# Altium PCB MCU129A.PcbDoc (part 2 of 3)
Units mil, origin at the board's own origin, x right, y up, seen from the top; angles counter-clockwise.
Board outline 3092.79 x 1702.62 mil, 4 copper layers (Top Layer, L2_GND, L3_PWR/SIG, Bottom Layer), stack 58.736 mil thick; 213 components, 108 nets, 914 pads, 219 vias.
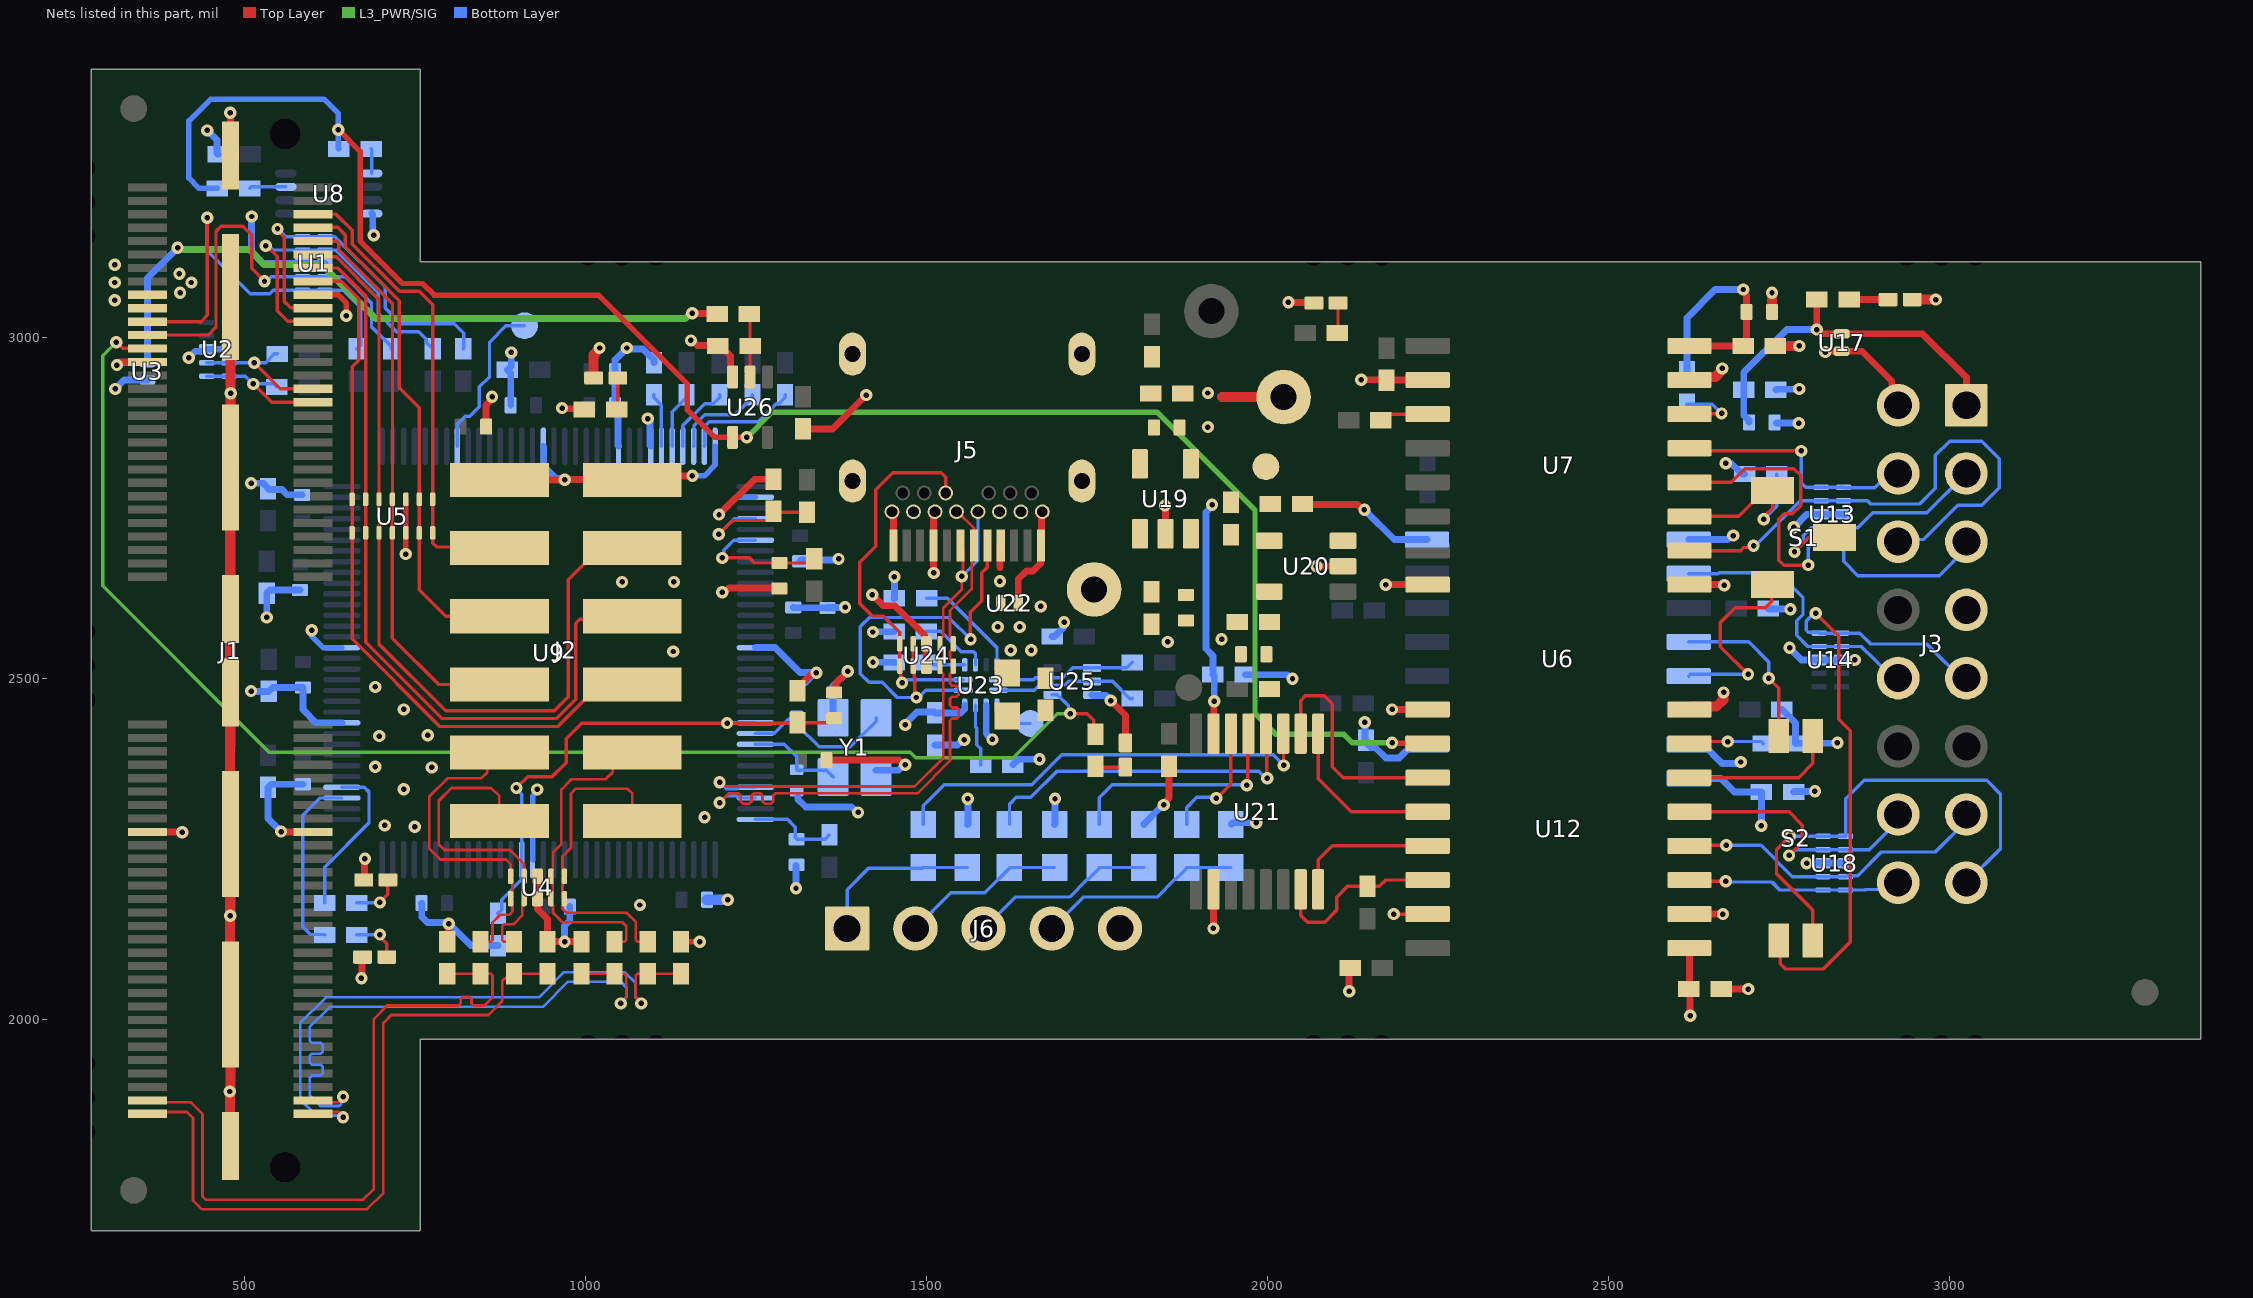
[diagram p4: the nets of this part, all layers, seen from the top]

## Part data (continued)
U6 U7: library part CMP-0091558-3, "Hot-swappable bidirectional I2C isolator with GPIO and enhanced EMC", Manufacturer="Texas Instruments", Operating Temperature Range=to
U8: library part CMP-0051824-2, "Dual Bus Buffer Gate With 3-State Outputs, DCU0008A (VSSOP-8)", F @ Nom Voltage(Max)(Mhz)=150, Generic Part Number=SN74LVC2G126, ICC @ Nom Voltage(Max)(mA)=0.01, Manufacturer="Texas Instruments", Operating Temperature Range="-40 to 125 C", Rating=Catalog, tpd @ Nom Voltage(Max)(ns)=9.8,4.9,4,3.2, Voltage(Nom)(V)=1.8,2.5,3.3,5
U9: library part CMP-0077953-1, "MSP432E401YTPDT, PDT0128A (TQFP-128)", Alternate Manufacturer="Texas Instruments", Alternate PartNumber=MSP432E401YTPDTR
U12: library part CMP-0076064-3, "High-Speed, Low-Power, Robust EMC Quad-Channel Digital Isolator, DW0016B (SOIC-16)", Alternate Manufacturer="Texas Instruments", Alternate PartNumber=ISO7741DW, Operating Temperature Range="-55 to 125 C", Rating=Catalog
U19: library part CMP-0091939-1, "Linear Voltage Regulator IC Positive Fixed 1 Output 300mA SOT-23-5", Digikey Part Number=296-47851-1-ND, Dropout Voltage=260mV, Manufacturer="Texas Instruments", Max Supply Voltage=5.5V, Min Supply Voltage=2V, Mouser Part Number=595-TLV70333DBVR, Nominal Supply Current=35-370uA, Operating Temperature Range="-40°C to +125°C", Output Voltage=3.3V
U20: library part CMP-0079364-1, "0.2% 50ppm/°C Drift Precision Series Voltage Reference with Shutdown Enable, DBV0005A (SOT-23-5)", Alternate Manufacturer="Texas Instruments", Alternate PartNumber=LM4120IM5X-4.1/NOPB
U21: library part CMP-0097843-1, "DAC 8-CH Resistor-String 12-bit 16-Pin TSSOP Rail", Digikey Part Number=DAC128S085CIMT/NOPB-ND, Manufacturer="Texas Instruments", Max Supply Voltage=5.5V, Min Supply Voltage=2.7V, Mouser Part Number=926-DAC128S085CIMTNO, Nominal Supply Current=460-650uA, Operating Temperature Range="-40°C to +125°C"
U23: library part CMP-0073635-2, "USB Type-C Configuration Channel Logic and Port Control, RWB0012A (X2QFN-12)", Alternate Manufacturer="Texas Instruments", Operating Temperature Range="-40 to 85 C", Rating=Catalog
U25: library part CMP-0051530-2, "Single 2-Input Positive-NOR Gate, DRL0005A, LARGE T&R", Alternate Manufacturer="Texas Instruments", F @ Nom Voltage(Max)(Mhz)=75, Generic Part Number=SN74AHC1G02, ICC @ Nom Voltage(Max)(mA)=0.01, Operating Temperature Range(C)="-40 to 125,-40 to 85", Rating=Catalog, tpd @ Nom Voltage(Max)(ns)=11.4,7.5, Voltage(Nom)(V)=3.3,5
U26: library part CMP-0051684-3, "Single Inverter, DCK0005A, LARGE T&R", F @ Nom Voltage(Max)(Mhz)=150, Generic Part Number=SN74LVC1G04, ICC @ Nom Voltage(Max)(mA)=0.01, Manufacturer="Texas Instruments", Operating Temperature Range(C)="-40 to 125,-40 to 85", Rating=Catalog, tpd @ Nom Voltage(Max)(ns)=7.5,5.2,4.2,3.7, Voltage(Nom)(V)=1.8,2.5,3.3,5
Y1: library part CMP-0094478-1, "Crystal 16 MHz ±20ppm Crystal 8pF 70 Ohms 4-SMD, No Lead", Digikey Part Number=732-830064296CT-ND, Frequency Stability=20ppm, Frequency_Fixed=16MHz, Load Capacitance=8pF, Manufacturer=Wurth, Mouser Part Number=710-830064296, Operating Temperature Range="-10°C to +70°C"
ZZ1: library part CMP-0003616-3
ZZ2: library part CMP-0077236-1
ZZ3: library part CMP-0077237-1
ZZ4: library part CMP-0077238-1

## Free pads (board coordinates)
  round 160 hole 160 unplated: 2(116.71,6382.89) 2(127.14,117.68) 2(4120.5,117.49) 2(4120.69,6382.89)

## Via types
v1: diameter 18, hole 8, Top Layer to Bottom Layer, tented both sides, 219 vias

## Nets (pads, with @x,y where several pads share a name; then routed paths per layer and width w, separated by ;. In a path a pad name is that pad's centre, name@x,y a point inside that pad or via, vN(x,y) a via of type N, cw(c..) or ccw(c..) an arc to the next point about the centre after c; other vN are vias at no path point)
3V3_OUT: J1.28 R53.2 U3.1 | length 1115.9
  Top Layer w10: v1(313.18,2960.12) 317.73,2964.68 J1.28@357.99,2964.68 ; v1(1156.62,3035.9) 1156.98,3035.54 1192.83,3035.54 R53.2@1193.19,3035.18
  L3_PWR/SIG w10: v1@402.07,3129.48 507.45,3129.48 529.79,3107.14 613.9,3107.14 692.62,3028.42 1146.97,3028.42 1154.45,3035.9 v1(1156.62,3035.9)
  Bottom Layer w10: v1(313.18,2960.12) 315.34,2960.12 319.01,2963.79 U3.1@357.99,2963.79 357.99,3087.93 v1(402.07,3132)
3V3_OUT_INV: R30.2 R31.2 U12.10 U26.4 | length 2699.8
  Top Layer w8: v1(637.81,3305.18) 669.7,3273.29 669.7,3142.25 732.24,3079.71 761.47,3079.71 778.61,3062.57 1019.51,3062.57 1149.25,2932.83 1149.25,2894.64 1189.81,2854.08 U26.4@1215.84,2854.08 1215.94,2854.18 v1(1236.81,2854.18) ; v1(2182.81,2406.18) 2183.31,2405.68 2234.44,2405.68 U12.10@2234.94,2405.18
  L3_PWR/SIG w8: v1(1236.81,2854.18) 1273.81,2891.18 1837.87,2891.18 1981.77,2747.28 1981.77,2448.99 2011.84,2418.92 2111.86,2418.92 2124.6,2406.18 v1(2182.81,2406.18)
  Bottom Layer w8: R31.2@460.56,3219.18 433.72,3219.18 418.81,3234.09 418.81,3318.18 450.81,3350.18 616.81,3350.18 637.81,3329.18 v1(637.81,3305.18) 637.81,3277.94 R30.2@638.56,3277.18
15W_PD: J1.26 R52.2 U25.4 | length 2066.4
  Top Layer w5: v1(312.19,2993.45) 313.18,2993.45 321.95,2984.68 J1.26@357.68,2984.68 ; v1(1710.81,2449.18) 1735.81,2449.18 1745.49,2439.5 1745.49,2421.5 R52.2@1747.81,2419.18
  L3_PWR/SIG w5: v1(312.19,2993.45) 292.31,2973.57 292.31,2636.52 536.15,2392.68 1476.47,2392.68 1484.47,2384.68 1627.31,2384.68 1691.81,2449.18 v1(1710.81,2449.18)
  Bottom Layer w5: U25.4@1684.67,2476.71 1691.96,2476.71 1708.32,2460.35 1708.32,2451.67 v1(1710.81,2449.18)
+5V0: C49.1 C52.2 C53.2 C59.2 J1.18 J1.20 J5.A4 J5.A9 J5.B4 J5.B9 L3.1 R39.2 R40.2 R46.1 R49.1 TP3.1 U19.1 U19.3 U22.1 U23.12 | length 325.4
  Top Layer w10: v1(965.86,2897.13) 966.87,2896.13 997.61,2896.13 R39.2@998.61,2895.12 ; v1(1510.61,2655.38) J5.A9@1510.61,2695.49 1510.61,2743.13 J5.B4@1512.57,2745.1 ; 1608.12,2663.51 1608.12,2694.59 J5.A4@1609.03,2695.49
  Bottom Layer w10: v1(1421.58,2568.73) 1422.04,2569.19 1452.27,2569.19 R46.1@1452.73,2569.66 ; R49.1@1452.73,2617.73 R49.1@1453.19,2618.18 ; R49.1@1453.19,2618.18 v1(1453.16,2649.76) ; v1@1468.81,2432.21 v1(1469.09,2432.49) 1469.09,2434.63 1486.01,2451.56 1511.43,2451.56 C59.2@1512.81,2450.18 1550.38,2450.18 1556.24,2456.04 U23.12@1556.24,2461.46
  other v1: 1623.81,2542.18 1653.81,2542.18 1604.81,2576.18 1636.81,2576.18 1667.81,2606.18 1607.81,2643.18 309.81,3055.18 405.81,3066.18 309.81,3081.18 422.47,3081.18 404.81,3094.18 309.81,3107.18
+5V0_A: C56.1 C57.2 L3.2 TP6.1 U20.3 U20.4 U21.7 | length 344.7
  Top Layer w10: U21.7@1920.89,2419.74 1921.43,2420.28 1921.43,2466.81 v1(1921.97,2467.34)
  Bottom Layer w10: v1(1918.81,2755.18) 1918.81,2753.32 1909.81,2744.32 1909.81,2544.18 1920.19,2533.8 C57.2@1920.19,2506.18 1921.97,2504.4 v1(1921.97,2467.34)
A_IN1_CONN: C1.2 J1.119 R7.2 | length 909.5
  Top Layer w4: J1.119@600.99,1862.32 603.83,1865.16 638.81,1865.16 644.81,1859.16 v1(644.81,1857.16) ; v1(1081.96,2024.18) 1073.96,2032.18 1073.96,2065.22 1076.3,2067.56 R7.2@1091.46,2067.56 C1.2@1140.46,2067.56
  Bottom Layer w4: v1(644.81,1857.16) 642.13,1859.84 605.67,1859.84 581.81,1883.7 581.81,1958.18 581.81,1995.18 619.81,2033.18 931.81,2033.18 968.65,2070.03 1057.65,2070.03 1073.96,2053.71 1073.96,2033.52 1081.96,2025.52 v1(1081.96,2024.18)
A_IN2_CONN: C3.1 J1.117 R9.2 | length 909.7
  Top Layer w4: J1.117@600.99,1882 603.83,1879.16 638.81,1879.16 644.81,1885.16 v1(644.81,1887.16) ; C3.1@994.46,2067.56 R9.2@1042.46,2067.56 1057.62,2067.56 1059.96,2065.22 1059.96,2032.18 v1(1051.96,2024.18)
  Bottom Layer w4: v1(644.81,1887.16) 642.13,1884.48 642.13,1876.79 639.18,1873.84 611.47,1873.84 595.81,1889.5 595.81,1897.16 595.81,1915.16 599.01,1918.36 611.82,1918.36 615.02,1921.56 615.02,1931.16 611.82,1934.36 599.01,1934.36 595.81,1937.56 595.81,1947.16 599.01,1950.36 611.82,1950.36 615.02,1953.56 615.02,1963.16 611.82,1966.36 599.01,1966.36 595.81,1969.56 595.81,1983.85 595.81,1989.38 625.61,2019.18 937.61,2019.18 974.45,2056.03 1051.85,2056.03 1059.96,2047.91 1059.96,2033.52 1051.96,2025.52 v1(1051.96,2024.18)
A_IN5_CONN: C2.1 J1.120 R8.1 | length 1024
  Top Layer w4: J1.120@357.99,1862.32 360.84,1865.16 416.03,1865.16 424.81,1856.38 424.81,1735.21 437.49,1722.53 680.06,1722.53 703.81,1746.27 703.81,1995.61 715.38,2007.18 812.01,2007.18 857.76,2007.18 878.11,2027.53 878.11,2057.03 888.64,2067.56 R8.1@895.46,2067.56 C2.1@944.46,2067.56
A_IN6_CONN: C4.1 J1.118 R10.1 | length 1023.1
  Top Layer w4: J1.118@357.99,1882 360.84,1879.16 421.83,1879.16 438.81,1862.18 438.81,1741 443.28,1736.53 674.26,1736.53 689.81,1752.07 689.81,2001.41 709.58,2021.18 812.01,2021.18 814.01,2021.18 817.21,2024.38 817.21,2030.43 820.41,2033.63 830.01,2033.63 833.21,2030.43 833.21,2024.38 836.41,2021.18 841.34,2021.18 851.96,2021.18 863.96,2033.18 863.96,2065.22 861.62,2067.56 R10.1@846.46,2067.56 C4.1@797.46,2067.56
ANALOG_IN_1: J2.1 R7.1 U4.1 U4.10 | length 475.2
  Top Layer w4: J2.1@1068.81,2291.83 1068.81,2331.94 1061.8,2338.95 985.8,2338.95 978.81,2331.96 978.81,2252.38 966.34,2239.91 966.34,2222.08 967.24,2221.18 967.24,2212.56 U4.1@969.18,2210.62 967.24,2208.68 967.24,2200.06 966.34,2199.15 966.34,2189.21 967.24,2188.3 967.24,2179.68 U4.10@969.18,2177.74 969.18,2170.56 966.42,2167.8 966.42,2162.97 972.2,2157.18 1060.28,2157.18 1073.96,2143.5 1073.96,2117.15 1076.3,2114.8 R7.1@1091.46,2114.8
ANALOG_IN_2: J2.3 R9.1 U4.2 U4.9 | length 474.8
  Top Layer w4: R9.1@1042.46,2114.8 1057.62,2114.8 1059.96,2117.15 1059.96,2137.7 1054.48,2143.18 966.4,2143.18 952.42,2157.17 952.42,2167.64 949.49,2170.56 U4.9@949.49,2177.74 951.43,2179.68 951.43,2188.3 952.34,2189.21 952.34,2199.15 951.43,2200.06 951.43,2208.68 U4.2@949.49,2210.62 951.43,2212.56 951.43,2221.18 952.34,2222.08 952.34,2245.71 964.81,2258.18 964.81,2337.76 980,2352.95 1029.93,2352.95 1040.15,2363.17 1040.15,2368.83 1063.15,2391.83 J2.3@1068.81,2391.83
ANALOG_IN_5: J2.2 R8.2 U4.4 U4.7 | length 492.3
  Top Layer w4: J2.2@873.93,2291.83 873.93,2328.06 861.81,2340.18 803.82,2340.18 785.03,2321.39 785.03,2257.37 793.22,2249.18 889.37,2249.18 910.12,2228.43 U4.4@910.12,2210.62 908.19,2208.68 908.19,2200.06 907.28,2199.15 907.28,2189.21 908.19,2188.3 908.19,2179.68 U4.7@910.12,2177.74 908.19,2175.81 908.19,2167.18 907.28,2166.28 907.28,2153.07 894.39,2140.18 880.96,2140.18 877.96,2137.18 877.96,2117.15 880.3,2114.8 R8.2@895.46,2114.8
ANALOG_IN_6: J2.4 R10.2 U4.5 U4.6 | length 492.3
  Top Layer w4: R10.2@846.46,2114.8 861.62,2114.8 863.96,2117.15 863.96,2142.98 875.16,2154.18 888.59,2154.18 893.28,2158.87 893.28,2166.28 892.38,2167.18 892.38,2175.81 U4.6@890.44,2177.74 892.38,2179.68 892.38,2188.3 893.28,2189.21 893.28,2199.15 892.38,2200.06 892.38,2208.68 U4.5@890.44,2210.62 890.44,2228.32 883.57,2235.18 787.42,2235.18 771.03,2251.57 771.03,2327.19 798.02,2354.18 847.26,2354.18 856.25,2363.17 856.25,2372.51 J2.4@873.93,2390.18
DAC_CLK: U12.13 U21.16 | length 212.4
  Top Layer w5: U21.16@2074.44,2191.39 2074.44,2234.81 2094.81,2255.18 U12.13@2234.94,2255.18
DAC_PICO: U12.12 U21.1 | length 246.7
  Top Layer w5: U21.1@2074.44,2419.74 2074.44,2353.66 2122.91,2305.18 U12.12@2234.94,2305.18
DAC_POCI: U12.11 U21.2 | length 341
  Top Layer w5: U21.2@2048.85,2419.74 2048.85,2468.22 2055.72,2475.09 2083.47,2475.09 2095.31,2463.25 2095.31,2371.28 2111.41,2355.18 U12.11@2234.94,2355.18
DAC_STE: R27.1 U12.14 U21.15 | length 265.3
  Top Layer w5: U21.15@2048.85,2191.39 2048.85,2153.07 2058.74,2143.18 2083.81,2143.18 2101.81,2161.18 2101.81,2180.18 2117.43,2195.8 R27.1@2146.81,2195.8 2164.03,2195.8 2173.41,2205.18 U12.14@2234.94,2205.18
DBG_ID4: R15.2 U9.63 | length 168.9
  Bottom Layer w5: U9.63@1174.52,2841.18 1174.83,2841.48 1174.83,2870.67 1181.39,2877.24 1253.49,2877.24 1279.56,2903.31 1283.5,2903.31 1292.81,2912.62 R15.2@1292.81,2916.56
DBG_ID5: R16.2 U9.62 | length 137.1
  Bottom Layer w5: U9.62@1158.78,2841.18 1159.33,2841.73 1159.33,2871.7 1174.87,2887.24 1219.43,2887.24 1235.5,2903.31 1244.81,2912.62 R16.2@1244.81,2916.56
DBG_ID6: R17.2 U9.61 | length 105.1
  Bottom Layer w5: U9.61@1143.03,2841.18 1143.03,2871.55 1174.79,2903.31 1187.5,2903.31 1196.81,2912.62 R17.2@1196.81,2916.56
DBG_ID7: R18.2 U9.60 | length 84.2
  Bottom Layer w5: U9.60@1127.28,2841.18 1127.28,2891.44 1148.46,2912.62 R18.2@1148.46,2916.56
DIGITAL_IO_2: J1.15 J2.5 U5.1 U5.14 | length 1069.6
  Top Layer w5: J1.15@600.99,3082.79 642.19,3082.79 667.75,3057.22 667.75,3040.43 667.93,3040.26 667.93,3024.93 667.75,3024.76 667.75,2967.39 658.07,2957.71 U5.14@658.07,2763.39 U5.1@658.07,2714.18 658.07,2614.18 658.07,2558.54 786.43,2430.18 959.72,2430.18 1021.37,2491.83 J2.5@1068.81,2491.83
DIGITAL_IO_3: J1.13 J2.7 U5.2 U5.13 | length 1165.8
  Top Layer w5: J1.13@600.99,3102.47 636.64,3102.47 677.75,3061.37 677.75,3044.57 677.93,3044.4 677.93,3020.79 677.75,3020.62 U5.13@677.75,2763.39 U5.2@677.75,2714.18 677.75,2614.18 677.75,2554.01 789.88,2441.88 957.28,2441.88 985.81,2470.41 985.81,2581.27 991.8,2587.26 1064.24,2587.26 J2.7@1068.81,2591.83
DIGITAL_IO_4: J1.11 J2.9 U5.3 U5.12 | length 1240.2
  Top Layer w5: J1.11@600.99,3122.16 604.49,3118.66 634.61,3118.66 697.44,3055.82 U5.12@697.44,2763.39 U5.3@697.44,2714.18 697.44,2614.18 697.44,2550.77 795.02,2453.18 954.44,2453.18 974.81,2473.55 974.81,2645.27 1021.37,2691.83 J2.9@1068.81,2691.83
DIGITAL_IO_5: J1.9 J2.6 U5.4 U5.11 | length 835.1
  Top Layer w5: J1.9@600.99,3141.84 635.27,3141.84 638.2,3138.92 638.2,3129.2 717.25,3050.15 U5.11@717.25,2763.52 ; U5.11@717.12,2763.39 U5.4@717.12,2714.18 717.12,2559.87 785.16,2491.83 J2.6@873.93,2491.83
DIGITAL_IO_7: J1.7 J2.8 U5.6 U5.9 | length 750.7
  Top Layer w5: J1.7@600.99,3161.53 601.49,3162.03 637.03,3162.03 648.2,3150.86 648.2,3133.34 727.25,3054.29 727.25,2927 756.49,2897.76 U5.9@756.49,2763.39 U5.6@756.49,2714.18 756.49,2630.55 795.22,2591.83 J2.8@873.93,2591.83
DIGITAL_IO_8: J1.5 J2.10 U5.7 U5.8 | length 692.5
  Top Layer w5: J1.5@600.99,3181.21 601.4,3181.63 634.1,3181.63 658.2,3157.53 658.2,3137.48 727.48,3068.21 756.7,3068.21 776.18,3048.74 U5.8@776.18,2763.39 U5.7@776.18,2714.18 776.18,2699.18 781.91,2693.45 872.31,2693.45 J2.10@873.93,2691.83
GND: C1.1 C2.2 C3.2 C4.2 C5.1 C10.2 C11.1 C14.2 C16.1 C17.2 C19.1 C20.1 C21.1 C22.1 C23.1 C24.1 C25.1 C26.1 C27.1 C30.1 C31.1 C32.1 C33.1 C34.1 C35.1 C36.1 C37.2 C38.2 C39.2 C40.2 C43.2 C44.1 C45.2 C46.1 C47.2 C48.1 C49.2 C50.2 C51.1 C52.1 C53.1 C54.1 C55.1 C56.2 C57.1 C58.1 C59.1 C60.2 C61.2 C62.2 C63.2 C64.1 C65.1 J1.17 J1.77 J1.78 J1.A1 J1.A2 J1.A3 J1.A4 J1.A5 J1.A6 J1.A7 J1.A8 J2.11 J2.12 J5.A1 J5.A12 J5.B1 J5.B12 J5.M1 J5.M2 J5.S1 J5.S2 J5.S3 J5.S4 J6.5 LED1.2 LED2.2 LED3.2 LED4.2 LED5.2 R26.1 R40.1 R47.2 R48.1 R54.1 TP5.1 U1.3@585.43,3109.19 U1.8@618.31,3109.19 U2.3@444.81,2983.19 U2.8@477.69,2983.19 U3.2 U4.3@929.81,2210.62 U4.8@929.81,2177.74 U5.5 U5.10 U6.2 U6.8 U7.2 U7.8 U8.4 U9.10 U9.17 U9.48 U9.55 U9.58 U9.64 U9.66 U9.80 U9.114 U12.9 U12.15 U19.2 U19.4 U20.2 U21.10 U22.2 U23.10 U24.3@1500.22,2551.47 U24.8@1500.22,2518.59 U25.3 U26.3 Y1.2 Y1.4 | length 6954.5
  Top Layer w5: v1(2185.3,2155.18) U12.15@2234.94,2155.18
  Top Layer w8: J1.17@601.01,3063.13 638.08,3063.13 649.4,3051.81 v1(649.43,3032.59) ; v1(736.81,2683.08) U5.5@736.81,2714.18 U5.10@736.81,2763.39 ; C1.1@1140.46,2114.8 v1(1167.79,2114.8)
  Top Layer w10: J1.78@357.99,2275.7 358.27,2275.42 408.53,2275.42 v1(408.81,2275.14) ; J1.A1@479.49,3267.43 v1(479.49,3330.18) ; v1(553.81,2276.18) 554.29,2275.7 J1.77@600.99,2275.7 ; v1(671.66,2061.18) 672.52,2062.04 672.52,2091.32 LED1.2@673.38,2092.18 ; LED2.2@675.09,2205.18 675.95,2206.04 675.95,2235.32 v1(676.81,2236.18) ; C4.2@797.46,2114.8 798.64,2115.98 798.64,2140.01 v1(799.81,2141.18) ; C25.1@854.53,2869.83 854.53,2901.45 863.15,2910.08 v1(863.15,2913.59) ; J2.12@873.93,2791.83 969.45,2791.83 v1(969.81,2792.18) 1068.45,2792.18 J2.11@1068.81,2791.83 1074.68,2797.7 v1(1157,2797.7) ; U4.3@929.81,2210.62 U4.8@929.81,2177.74 929.81,2162.8 944.46,2148.15 C2.2@944.46,2114.8 v1(969.46,2114.8) C3.2@994.46,2114.8 C3.2@995.84,2116.18 ; v1(1154.81,2996.18) 1156.86,2996.18 1164.36,2988.68 1193.69,2988.68 R54.1@1194.19,2988.18 1198.12,2988.18 1212.97,2973.34 1212.97,2945.54 U26.3@1215.84,2942.66 ; v1(1195.91,2740.9) 1247.69,2792.68 C48.1@1275.81,2792.68 ; v1@1202.21,2628.58 v1(1200.81,2627.18) 1204.33,2627.18 1210.65,2633.5 C16.1@1285.14,2633.5 ; C45.2@1311.31,2482.8 1311.31,2486.74 1332.22,2507.65 1337.28,2507.65 v1(1338.81,2509.18) ; C65.1@1318.81,2866.56 1362.19,2866.56 v1(1411.81,2916.18) ; C32.1@1353.51,2381.18 1459.64,2381.18 1466.64,2374.18 v1(1468.81,2374.18) ; C44.1@1360.81,2482.8 1367.62,2489.61 1367.62,2493.99 v1(1384.81,2511.18) ; v1(1420.81,2623.18) 1436.81,2607.18 1454.28,2607.18 1497.34,2564.12 1497.34,2554.34 U24.3@1500.22,2551.47 U24.8@1500.22,2518.59 ; J5.B1@1449.58,2745.1 1451.55,2743.13 J5.A12@1451.55,2695.49 ; U22.2@1634.6,2611.18 1634.6,2646.1 1646.68,2658.18 1656.17,2658.18 1667.18,2669.19 1667.18,2694.59 J5.A1@1668.09,2695.49 1668.99,2696.4 1668.99,2744.04 J5.B12@1670.05,2745.1 ; v1(1770.31,2468.18) 1791.81,2446.69 LED5.2@1791.81,2406.18 ; v1(1847.81,2315.18) 1847.81,2317.35 1855.67,2325.2 C58.1@1855.67,2372.12 ; v1(1849.81,2754.18) 1850.41,2753.58 U19.2@1850.41,2712.82 ; v1(1920.81,2134.18) 1920.89,2134.27 U21.10@1920.89,2191.39 ; v1(2030.81,3052.18) 2031.31,3051.68 2067.59,3051.68 LED4.2@2068.09,3051.18 ; C56.2@2051.43,2756.18 2051.81,2755.8 2132.19,2755.8 2140.12,2747.88 v1(2142.28,2747.88) ; v1(2071.81,2665.18) U20.2@2110.94,2665.18 ; v1(2119.81,2042.18) 2119.81,2074.8 C17.2@2121.19,2076.18 ; v1@2136.81,2939.18 v1(2137.43,2938.56) 2173.81,2938.56 2174.19,2938.18 U7.2@2234.88,2938.18 ; v1(2173.42,2638.18) U7.8@2234.88,2638.18 ; v1(2182.81,2455.18) U12.9@2234.94,2455.18
  Top Layer w15: J1.A2@479.15,3060.29 J1.A2@479.49,3059.95 479.65,3059.79 479.65,2917.34 479.81,2917.18 479.65,2917.02 479.65,2810.11 J1.A3@479.49,2809.95 479.49,2683.1 479.31,2682.92 479.31,2602.66 J1.A4@479.49,2602.47 J1.A5@479.49,2480.03 479.49,2400.71 478.81,2400.03 479.15,2399.69 479.15,2272.89 J1.A6@479.49,2272.55 479.49,2154.71 478.81,2154.03 478.81,2153.03 v1(479.15,2152.69) 479.15,2022.89 J1.A7@479.49,2022.55 479.81,2022.23 479.81,1896.03 v1(478.81,1895.03) 479.15,1894.69 479.15,1815.41 J1.A8@479.49,1815.07 ; LED3.2@1012.09,2941.18 1012.09,2975.65 1020.81,2984.37 v1(1020.81,2985.18) ; 1933.81,2913.18 TP5.1@2023.81,2913.18
  Bottom Layer w5: C11.1@1308.81,2226.48 C11.1@1309.81,2227.48
  Bottom Layer w8: v1(598.81,2571.18) 598.81,2562.54 615.38,2545.97 642.97,2545.97 U9.17@643.03,2545.91 ; U9.114@922.56,2234.88 922.56,2328.26 929.58,2335.28 v1(929.58,2337.95) ; v1(1157,2797.7) 1157.73,2798.44 1158.48,2797.69 1174.37,2797.69 1190.27,2813.6 U9.64@1190.27,2841.18 ; v1(1195.91,2740.9) 1221.39,2766.38 U9.66@1249.33,2766.38
  Bottom Layer w10: v1(310.81,2925.18) 323.83,2938.2 U3.2@357.99,2938.2 ; v1(418.48,2970.73) 418.75,2970.73 428.48,2980.46 442.09,2980.46 U2.3@444.81,2983.19 U2.8@477.69,2983.19 ; v1(445.81,3304.18) 459.86,3290.13 459.86,3270.89 C5.1@461.56,3269.18 ; v1(509.81,2482.18) 510.43,2481.56 C39.2@535.81,2481.56 541.73,2487.48 C22.1@585.81,2487.48 585.81,2455.18 605.32,2435.67 U9.10@643.03,2435.67 ; v1(509.89,2786.78) 528,2786.78 534.81,2779.97 C37.2@534.81,2778.8 535.81,2777.8 555.01,2777.8 562.93,2769.88 C24.1@584.81,2769.88 ; v1(510.81,3177.95) 510.58,3177.72 510.58,3126.35 527.73,3109.19 U1.3@585.43,3109.19 U1.8@618.31,3109.19 ; v1(532.81,2590.18) C38.2@532.81,2625.56 537.49,2630.24 C23.1@581.81,2630.24 ; v1(553.81,2276.18) 534.81,2295.18 C40.2@534.81,2340.94 539.36,2345.49 C46.1@586.05,2345.49 ; U8.4@686.81,3182.13 687.42,3182.13 688.26,3181.29 688.26,3151.98 v1(689.7,3150.53) ; C35.1@759.81,2171.18 760.18,2170.81 760.18,2150.81 768.28,2142.71 798.28,2142.71 832.05,2108.94 C43.2@871.81,2108.94 ; C26.1@890.49,2901.18 890.49,2948.26 C47.2@885.56,2953.18 891.31,2958.93 v1(891.31,2978.6) ; U9.48@938.3,2841.18 939.12,2840.37 939.12,2811.37 956.78,2793.71 968.28,2793.71 v1(969.81,2792.18) ; v1(969.46,2114.8) 969.46,2138.14 977.21,2145.89 C34.1@977.21,2166.18 ; U9.55@1048.54,2841.18 1047.99,2841.73 1047.99,2896.7 C27.1@1043.51,2901.18 C21.1@1043.51,2951.18 1043.51,2967.88 v1(1060.81,2985.18) 1062.34,2983.65 1084.55,2983.65 1100.46,2967.74 R26.1@1100.46,2963.8 ; v1@1078.51,2166.99 v1(1080.04,2168.52) ; v1(1091.35,2881.62) 1094.97,2878 1094.97,2841.99 U9.58@1095.78,2841.18 ; U9.80@1249.33,2545.91 1278.33,2545.91 1314.81,2509.42 1338.57,2509.42 v1(1338.81,2509.18) 1336.64,2509.18 1321.01,2493.55 1318.12,2493.55 1311.31,2486.74 C19.1@1311.31,2482.8 ; C31.1@1304.81,2604.88 1305.31,2604.38 1354.31,2604.38 C36.1@1354.81,2603.88 1355.46,2604.53 1380.16,2604.53 v1(1380.81,2605.18) ; v1(1308.81,2193.18) C11.1@1308.81,2226.48 ; C20.1@1311.31,2327.94 1311.31,2324 1323.12,2312.19 1389.95,2312.19 1397.96,2304.18 v1(1399.81,2304.18) ; C30.1@1314.81,2672.48 1316.48,2674.15 1369.51,2674.15 v1(1371.18,2675.83) ; Y1.4@1363.31,2452.8 1363.31,2489.68 v1(1384.81,2511.18) ; v1(1421.71,2524.48) 1421.86,2524.33 1453.03,2524.33 R47.2@1453.19,2524.18 ; Y1.2@1426.3,2366.18 1459.25,2366.18 1467.25,2374.18 v1(1468.81,2374.18) ; C59.1@1512.81,2402.94 1513.05,2403.18 1545.53,2403.18 1553.29,2410.94 v1(1555.46,2410.94) ; C60.2@1560.09,2286.49 1560.81,2287.21 v1(1560.81,2324.18) ; U23.10@1587.74,2461.46 1587.74,2420.25 v1(1596.81,2411.18) ; R48.1@1626.76,2374.18 1634.76,2382.18 v1(1665.81,2382.18) ; C64.1@1684.19,2562.18 1688.12,2562.18 1700.28,2574.34 1700.28,2581.65 v1(1701.81,2583.18) ; C61.2@1687.84,2286.49 1688.56,2287.21 v1(1688.56,2324.18) ; U25.3@1742.94,2476.71 1743.85,2475.8 1763.19,2475.8 1770.31,2468.68 v1(1770.31,2468.18) ; C62.2@1818.83,2286.49 1818.83,2287.47 1846.54,2315.18 v1(1847.81,2315.18) ; C63.2@1946.9,2286.85 1949.24,2289.18 v1(1983.81,2289.18) ; C57.1@1967.43,2506.18 2028.64,2506.18 2034.64,2500.18 v1(2036.81,2500.18) ; v1(2142.28,2747.88) 2185.98,2704.18 U6.8@2233.88,2704.18 ; v1@2142.81,2437.18 v1(2142.81,2436.37) 2143.31,2435.87 C10.2@2143.31,2410.3 ; C10.2@2144.81,2409.8 2144.81,2405.87 2151.62,2399.06 2158.69,2399.06 2173.56,2384.18 2193.21,2384.18 2213.21,2404.18 U6.2@2233.88,2404.18
  Bottom Layer w15: C33.1@1177.43,2176.18 v1(1208.81,2176.18)
  other v1: 749.81,2283.18 705.81,2285.18 1174.81,2297.18 733.81,2338.18 774.81,2370.18 691.81,2371.18 697.81,2416.18 768.81,2417.18 733.81,2455.18 691.81,2488.18 1128.81,2540.18 1853.81,2554.18 1932.81,2558.18 1053.81,2642.18 1129.81,2642.18 1912.81,2869.18 479.91,2918.84 1912.81,2919.18
GNDH: C9.1 C12.1 C13.1 C15.1 C18.1 J3.2 J3.7 LED6.2 U6.9 U6.15 U7.9 U7.15 U12.2 U12.8 U13.3@2811.93,2741.5 U13.8@2844.81,2741.5 U14.3@2841.81,2527.81 U14.8@2808.93,2527.81 U17.2 U18.3@2814.81,2229.87 U18.8@2847.68,2229.87 | length 983
  Top Layer w10: U7.9@2618.74,2638.18 2668.81,2638.18 v1(2669.81,2637.18) ; U12.2@2618.8,2155.18 v1(2667.81,2155.18) ; C18.1@2665.05,2045.18 v1(2704.81,2045.18) ; v1(2817.81,2979.18) 2819.01,2980.39 U17.2@2841.81,2980.39 2872.06,2980.39 2915.3,2937.15 2915.3,2902.88 J3.2@2920.45,2897.73
  Top Layer w15: U7.15@2618.74,2938.18 2623.05,2942.49 2656.52,2942.49 2666.23,2952.21 2666.23,2954.61 v1(2666.81,2955.18) ; U12.8@2618.8,2455.18 2623.11,2459.49 2658.52,2459.49 2668.23,2469.21 2668.23,2479.61 v1(2668.81,2480.18) ; C13.1@2739.81,3043.18 v1(2739.81,3066.18) ; C15.1@2744.81,2988.18 v1(2779.95,2988.18) ; LED6.2@2945.44,3056.18 v1(2979.81,3056.18)
  Bottom Layer w10: U6.15@2617.74,2404.18 2638.41,2404.18 2666.41,2376.18 2691.81,2376.18 v1(2693.81,2378.18) ; U6.9@2617.74,2704.18 2674.64,2704.18 2680.64,2710.18 v1(2682.81,2710.18) ; C12.1@2746.56,2874.99 v1(2779,2874.99) ; v1(2765.51,2545.86) 2765.51,2545.11 2782.81,2527.81 U14.3@2841.81,2527.81 v1(2861.31,2527.81) ; C9.1@2771.43,2334.18 2771.93,2334.68 2802.31,2334.68 v1(2802.81,2335.18) ; v1(2771.81,2722.18) 2791.12,2741.5 U13.3@2811.93,2741.5 U13.8@2844.81,2741.5 U13.8@2845.87,2740.43 ; v1(2790.49,2229.87) U18.3@2814.81,2229.87 U18.8@2847.68,2229.87 ; U18.8@2847.8,2229.79 U18.8@2853.8,2229.79
IO_TGT_V: C12.2 J3.1 L1.1 R32.2 U17.1 | length 542.5
  Top Layer w10: R32.2@2805.48,3056.18 v1(2805.48,3012.19) 2807.64,3012.19 2813.86,3005.98 U17.1@2841.81,3005.98 2960.71,3005.98 3024.81,2941.87 J3.1@3024.81,2901.18
  Bottom Layer w10: C12.2@2706.11,2876.18 2706.11,2879.13 2698.31,2886.93 L1.1@2698.31,2923.99 2698.31,2948.99 2761.51,3012.19 v1(2805.48,3012.19)
IO_TGT_V_FL: C9.2 C13.2 C15.2 C18.2 L1.2 R13.2 R14.2 R20.2 R23.2 R28.2 U6.16 U7.16 U12.1 | length 831.1
  Top Layer w10: U7.16@2618.74,2988.18 C15.2@2697.56,2988.18 2702.49,2993.1 C13.2@2702.49,3038.18 2702.49,3062.5 2697.56,3067.42 v1(2697.56,3070.94) ; U12.1@2618.8,2105.18 2618.8,2046.17 C18.2@2617.81,2045.18 2619.81,2043.18 v1(2619.81,2006.18)
  Bottom Layer w10: R23.2@2615.09,2949.99 2615.09,3029.47 2656.56,3070.94 v1(2697.56,3070.94) ; U6.16@2617.74,2354.18 2664.81,2354.18 2684.81,2334.18 C9.2@2724.19,2334.18 v1(2724.19,2284.8) ; v1(2671.81,2816.18) 2679.63,2816.18 2695.63,2800.18 R20.2@2699.56,2800.18 ; R14.2@2734.43,2603.18 2734.93,2602.68 2766.31,2602.68 v1(2766.81,2602.18) ; L1.2@2745.56,2923.99 2746.15,2924.59 2779.21,2924.59 v1(2779.81,2925.18) ; R13.2@2754.43,2455.18 2774.43,2435.18 R28.2@2774.43,2405.18 2774.93,2405.68 2835.31,2405.68 v1(2835.81,2406.18)
MCU_CLK_ISO: J3.13 U12.4 U18.2 U18.9 | length 464
  Top Layer w5: U12.4@2618.8,2255.18 2619.8,2256.18 v1(2672.81,2256.18)
  Bottom Layer w5: v1(2672.81,2256.18) 2723.74,2256.18 2769.74,2210.18 U18.2@2814.81,2210.18 U18.9@2847.68,2210.18 2849.12,2211.62 2865.25,2211.62 2899.81,2246.18 2979.3,2246.18 3024.3,2291.18 J3.13@3029.81,2291.18
MCU_PICO_ISO: J3.14 U12.5 U18.4 U18.7 | length 409.7
  Top Layer w5: U12.5@2618.8,2305.18 2764.81,2305.18 2784.31,2285.68 2784.31,2260.62 v1(2764.89,2241.2)
  Bottom Layer w5: v1(2764.89,2241.2) 2765.96,2241.2 2774.32,2249.55 U18.4@2814.81,2249.55 U18.7@2847.68,2249.55 2882.67,2249.55 2919.3,2286.18 J3.14@2929.81,2286.18
MCU_POCI_ISO: S2.1 U12.6 | length 229.7
  Top Layer w5: U12.6@2618.8,2355.18 2778.81,2355.18 2799.81,2376.18 S2.1@2799.81,2416.18
MCU_POCI_ISO_SW: J3.15 S2.4 U18.5 U18.6 | length 717.5
  Top Layer w5: v1(2765.81,2269.18) 2746.39,2249.76 2746.39,2214.6 2799.81,2161.18 S2.4@2799.81,2116.18
  Bottom Layer w5: v1(2765.81,2269.18) U18.5@2814.78,2269.21 ; U18.5@2814.81,2269.24 U18.6@2847.68,2269.24 2847.68,2324.06 2875.16,2351.53 3054.46,2351.53 3074.81,2331.18 3074.81,2251.18 J3.15@3024.81,2201.18
MCU_RXD: J1.33 R6.2 U2.1 U2.10 | length 208.4
  Top Layer w5: v1(513.12,2932.46) 539.96,2905.62 J1.33@600.99,2905.62
  Bottom Layer w5: U2.1@444.81,2943.82 U2.10@477.69,2943.82 501.14,2943.82 512.5,2932.46 v1(513.12,2932.46) 543.33,2932.46 R6.2@547.71,2928.08
MCU_RXD_ISO: S2.2 U6.12 | length 244.3
  Top Layer w5: v1(2735.18,2500.77) 2749.81,2486.14 S2.2@2749.81,2416.18
  Bottom Layer w5: U6.12@2617.74,2554.18 2705.81,2554.18 2735.18,2524.81 v1(2735.18,2500.77)
MCU_RXD_ISO_SW: J3.9 S2.3 U14.1 U14.10 | length 963.8
  Top Layer w5: S2.3@2749.81,2116.18 2751.81,2114.18 2751.81,2082.64 2759.77,2074.68 2814.77,2074.68 2854.31,2114.22 2854.31,2424.06 2837.55,2440.82 2837.55,2562.44 v1(2803.81,2596.18)
  Bottom Layer w5: v1(2803.81,2596.18) 2801.11,2596.18 2789.81,2584.88 2789.81,2571.55 2792.74,2568.62 2807.5,2568.62 U14.10@2808.93,2567.18 U14.1@2841.81,2567.18 2868.31,2567.18 2884.31,2551.18 2967,2551.18 3024.81,2493.37 J3.9@3024.81,2491.18 ; J3.9@3007,2491.18 J3.9@3009.81,2491.18
MCU_STE_ISO: J3.16 U12.3 U18.1 U18.10 | length 312.4
  Top Layer w5: U12.3@2618.8,2205.18 2620.8,2203.18 v1(2671.81,2203.18)
  Bottom Layer w5: v1(2671.81,2203.18) 2672.81,2202.18 2739.81,2202.18 2751.49,2190.5 U18.1@2814.81,2190.5 U18.10@2847.68,2190.5 2876.5,2190.5 2877.19,2191.18 J3.16@2924.81,2191.18
MCU_TCK: J1.22 R3.1 U1.1 U1.10 | length 610.2
  Top Layer w5: J1.22@358.19,3023.93 436.58,3023.93 445.81,3033.16 v1(445.81,3176.22)
  Bottom Layer w5: v1(445.81,3176.22) 445.81,3127.56 508.84,3064.53 537.21,3064.53 542.5,3069.82 U1.1@585.43,3069.82 U1.10@618.31,3069.82 645.4,3069.82 671.06,3044.17 671.06,2990.19 R3.1@664.81,2983.94
MCU_TCK_ISO: J3.4 U7.13 U13.5 U13.6 | length 366.2
  Top Layer w5: U7.13@2618.74,2838.18 2622.24,2834.68 2782.31,2834.68 v1(2782.81,2834.18)
  Bottom Layer w5: v1(2782.81,2834.18) 2782.81,2787.18 2789.12,2780.87 U13.5@2811.93,2780.87 U13.6@2844.81,2780.87 2845.32,2780.36 2890.76,2780.36 2911.59,2801.18 J3.4@2924.81,2801.18
MCU_TDI: J1.19 R1.2 U1.5 U1.6 | length 535.2
  Top Layer w5: v1(548.61,3159.78) 548.61,3157.25 558.63,3147.23 558.63,3053.32 567.87,3044.08 600.33,3044.08 J1.19@600.99,3043.42
  Bottom Layer w5: v1(548.61,3159.78) 549.52,3159.78 560.73,3148.56 U1.5@585.43,3148.56 U1.6@618.31,3148.56 618.44,3148.43 632.68,3148.43 706.45,3074.66 706.45,3043.77 729.29,3020.92 807.94,3020.92 821.99,3006.88 821.99,2984.89 R1.2@821.04,2983.94
MCU_TDI_ISO: J3.5 U7.12 U13.1 U13.10 | length 682.8
  Top Layer w5: U7.12@2618.74,2788.18 2679.81,2788.18 2699.81,2808.18 2772.01,2808.18 2781.81,2798.38 2781.81,2753.98 2769.74,2741.91 2757.54,2741.91 2749.81,2734.18 2749.81,2674.18 2757.07,2666.92 v1(2793.13,2666.92)
  Bottom Layer w5: v1(2793.13,2666.92) 2793.13,2692.48 2801.34,2700.69 2810.5,2700.69 U13.1@2811.93,2702.13 U13.10@2844.81,2702.13 2844.81,2672.2 2865.83,2651.18 2984.81,2651.18 J3.5@3024.81,2691.18
MCU_TDO: J1.21 R2.2 U1.4 U1.7 | length 489.8
  Top Layer w5: v1(531.58,3135.04) 532.8,3135.04 548.23,3119.61 548.23,3039.56 563.7,3024.08 J1.21@600.64,3024.08
  Bottom Layer w5: v1(531.58,3135.04) 535.1,3135.04 541.26,3128.88 U1.4@585.43,3128.88 U1.7@618.31,3128.88 634,3128.88 696.45,3066.43 696.45,3035.86 723.06,3009.25 755.51,3009.25 766.92,2997.84 766.92,2993.25 R2.2@776.23,2983.94
MCU_TDO_ISO: J3.6 U7.10 U13.4 U13.7 | length 790.3
  Top Layer w5: U7.10@2618.74,2688.18 2693.81,2688.18 2698.32,2692.69 2710.32,2692.69 v1(2712.81,2695.18)
  Bottom Layer w5: v1(2712.81,2695.18) 2714.97,2695.18 2780.97,2761.18 U13.4@2811.93,2761.18 2861.71,2761.18 2879.81,2761.18 2884.54,2756.45 2956.67,2756.45 2979.43,2779.21 2979.43,2827.85 3000.25,2848.68 3047.31,2848.68 3073.09,2822.9 3073.09,2780.31 3047.31,2754.54 3011.95,2754.54 2961.74,2704.33 2937.45,2704.33 J3.6@2925.65,2692.53
MCU_TMS: J1.24 R4.1 U1.2 U1.9 | length 636.6
  Top Layer w5: J1.24@357.99,3004.05 358.1,3004.16 447,3004.16 458.39,3015.55 458.39,3156 466.13,3163.73 497.96,3163.73 510.64,3151.06 510.64,3101.94 v1(529.55,3083.03)
  Bottom Layer w5: v1(529.55,3083.03) 533.07,3083.03 539.54,3089.51 U1.2@585.43,3089.51 U1.9@618.31,3089.51 625.49,3089.51 647.96,3089.51 686.45,3051.02 686.45,3016.47 715.05,2987.88 R4.1@715.05,2983.94
MCU_TMS_2W_ISO: R20.1 S1.1 U7.11 | length 261.2
  Top Layer w5: U7.11@2618.74,2738.18 2691,2738.18 2729,2776.18 S1.1@2740.81,2776.18 2740.81,2750.52 2727.81,2737.52 v1(2727.81,2734.18)
  Bottom Layer w5: v1@2729.81,2731.18 2729.81,2736.18 2746.81,2753.18 R20.1@2746.81,2800.18
MCU_TMS_4W_ISO: S1.3 U6.13 | length 294
  Top Layer w5: v1(2704.66,2506.66) 2664.12,2547.2 2664.12,2582.66 2685.86,2604.39 2729.88,2604.39 2739.62,2614.13 2739.62,2637.2 S1.3@2740.81,2638.39
  Bottom Layer w5: U6.13@2617.74,2504.18 2620.22,2506.66 v1(2704.66,2506.66)
MCU_TMS_ISO: J3.3 S1.2 U13.2 U13.9 | length 373.3
  Top Layer w5: v1(2772.81,2686.18) 2793.91,2707.28 S1.2@2831.36,2707.28
  Bottom Layer w5: v1(2772.81,2686.18) 2772.81,2686.3 2785.81,2699.3 2785.81,2710.02 2797.51,2721.72 2811.84,2721.72 U13.2@2811.93,2721.81 U13.9@2844.81,2721.81 2865.82,2721.81 2887.39,2743.38 2967.01,2743.38 J3.3@3024.81,2801.18
MCU_TXD: J1.31 R5.2 U2.2 U2.9 | length 211
  Top Layer w5: v1(514.39,2963.5) 552.58,2925.31 J1.31@600.99,2925.31
  Bottom Layer w5: U2.2@444.81,2963.5 U2.9@477.69,2963.5 v1(514.39,2963.5) 531.09,2963.5 544.07,2976.48 R5.2@548,2976.48
MCU_TXD_ISO: J3.10 U6.10 U14.2 U14.9 | length 422.4
  Bottom Layer w5: U6.10@2617.74,2654.18 2660.65,2654.18 2662.15,2655.68 2748.31,2655.68 2785.31,2618.68 2785.31,2594.52 2775.81,2585.02 2775.81,2564.18 2792.49,2547.5 U14.9@2808.93,2547.5 U14.2@2841.81,2547.5 2870.52,2547.5 2873.45,2544.57 2874.69,2543.13 ccw(c2905.65,2570.03) 2879.91,2538.1 2924.81,2493.2 J3.10@2924.81,2491.18
NetC11_2: C11.2 R19.2 U9.96 | length 132.3
  Bottom Layer w5: U9.96@1249.33,2293.94 1296.39,2293.94 1307.68,2282.65 1307.68,2267.01 C11.2@1309.81,2264.88 1351.51,2264.88 R19.2@1357.81,2271.18
NetC16_2: C16.2 R25.1 U9.70 | length 205.3
  Top Layer w5: v1(1200.81,2677.33) 1240.61,2677.33 1248.06,2669.88 C16.2@1284.81,2669.88 1329.57,2669.88 R25.1@1335.62,2675.93
  Bottom Layer w5: v1(1200.81,2677.33) 1202.67,2679.19 1202.67,2688.8 1217.26,2703.39 U9.70@1249.33,2703.39
NetC19_2: C19.2 U9.88 Y1.1 | length 234
  Bottom Layer w5: U9.88@1249.33,2419.92 1249.88,2420.47 1276.91,2420.47 1297.25,2440.82 1305.19,2440.82 C19.2@1309.81,2445.43 1311.31,2443.93 1311.31,2431.62 1342.69,2400.24 1388.66,2400.24 1426.3,2437.87 Y1.1@1426.3,2442.8
NetC20_2: C20.2 U9.89 Y1.3 | length 145.1
  Bottom Layer w5: U9.89@1249.33,2404.17 1291.82,2404.17 1309.81,2386.18 C20.2@1309.81,2366.93 1310.56,2366.18 1353.31,2366.18 Y1.3@1363.31,2356.18
NetC43_1: C43.1 C44.2 C45.1 U9.87 U9.115 | length 772.2
  Top Layer w5: v1(898.94,2340.14) 915.25,2356.45 951.08,2356.45 971.94,2377.32 971.94,2412.32 994.81,2435.18 v1(1207.81,2435.18) 1310.93,2435.18 C45.1@1311.31,2435.56 1354.93,2435.56 1361.86,2442.48 C44.2@1364.81,2442.48
  Bottom Layer w5: C43.1@871.81,2156.18 877.13,2161.5 877.13,2176.5 906.26,2205.63 906.26,2234.33 U9.115@906.81,2234.88 906.81,2330.71 898.94,2338.58 v1(898.94,2340.14) ; v1(1207.81,2435.18) 1208.3,2435.67 U9.87@1249.33,2435.67
NetC48_2: C48.2 R37.1 U9.68 | length 207.7
  Top Layer w5: v1(1195.54,2711.92) 1215.91,2732.29 1266.42,2732.29 1275.73,2741.6 C48.2@1275.73,2745.54 ; C48.2@1276.84,2744.43 R37.1@1324.81,2744.43
  Bottom Layer w5: v1(1195.54,2711.92) 1218.5,2734.88 U9.68@1249.33,2734.88
NetC50_1: C50.1 C51.2 R38.2 U20.5
NetC54_2: C54.2 C55.2 L2.1 U19.5
NetC60_1: C60.1 J6.1 R42.1 | length 246.7
  Bottom Layer w5: J6.1@1383.81,2134.03 1383.81,2191.04 1415.09,2222.32 1494.2,2222.32 R42.1@1495.38,2223.5 C60.1@1560.09,2223.5
NetC61_1: C61.1 J6.2 R43.1 | length 241.7
  Bottom Layer w5: J6.2@1483.81,2134.03 1535.96,2186.18 1585.51,2186.18 1621.84,2222.51 R43.1@1621.84,2223.5 C61.1@1687.84,2223.5
NetC62_1: C62.1 J6.3 R44.1 | length 272.7
  Bottom Layer w5: J6.3@1583.81,2134.03 1629.96,2180.18 1709.88,2180.18 1736.01,2206.31 1736.99,2206.31 1753.19,2222.51 R44.1@1753.19,2223.5 C62.1@1818.83,2223.5
NetC63_1: C63.1 J6.4 R45.1 | length 300.4
  Bottom Layer w5: J6.4@1683.81,2134.03 1729.96,2180.18 1838.23,2180.18 1864.36,2206.31 1865.34,2206.31 1881.54,2222.51 R45.1@1881.54,2223.5 C63.1@1946.54,2223.5
NetLED1_1: LED1.1 R21.1 | length 71.2
  Top Layer w5: v1(698.81,2125.18) 698.81,2121.85 708.81,2111.85 LED1.1@708.81,2092.18
  Bottom Layer w5: R21.1@664.93,2124.63 698.26,2124.63 v1(698.81,2125.18)
NetLED2_1: LED2.1 R22.1 | length 71.9
  Top Layer w5: v1(698.81,2172.23) 710.52,2183.95 LED2.1@710.52,2205.18
  Bottom Layer w5: R22.1@664.93,2171.68 698.26,2171.68 v1(698.81,2172.23)
NetLED3_1: LED3.1 R39.1 | length 46.8
  Top Layer w5: R39.1@1045.86,2895.12 1047.52,2896.79 LED3.1@1047.52,2941.18
NetLED4_1: LED4.1 R41.1 | length 44.5
  Top Layer w5: R41.1@2102.43,3007.18 2103.52,3008.28 LED4.1@2103.52,3051.18
NetLED5_1: LED5.1 R52.1 | length 44.5
  Top Layer w5: R52.1@1747.81,2371.94 1749,2370.75 LED5.1@1791.81,2370.75
NetLED6_1: LED6.1 R32.1 | length 57.3
  Top Layer w10: R32.1@2852.72,3056.18 LED6.1@2910.01,3056.18
NetR21_2: R21.2 U9.3 | length 267.9
  Bottom Layer w5: R21.2@617.69,2124.63 617.14,2125.18 597.37,2125.18 585.81,2136.74 585.81,2299.93 611.31,2325.43 U9.3@643.03,2325.43
NetR22_2: R22.2 U9.4 | length 232.2
  Bottom Layer w5: R22.2@617.69,2171.68 617.69,2224.06 682.81,2289.18 682.81,2334.18 675.81,2341.18 U9.4@643.03,2341.18
NetR23_1: R23.1 U7.14 | length 100.8
  Top Layer w5: U7.14@2618.74,2888.18 2619.24,2888.68 2665.31,2888.68 v1(2665.81,2889.18)
  Bottom Layer w5: R23.1@2615.09,2902.75 2652.24,2902.75 2661.56,2893.43 2661.56,2892.94 v1@2659.81,2891.18
NetR26_2: R26.2 U9.59 | length 80
  Bottom Layer w5: R26.2@1100.46,2916.56 1100.46,2912.62 1111.53,2901.55 U9.59@1111.53,2841.18
NetR28_1: R28.1 U12.7 | length 110.9
  Top Layer w5: U12.7@2618.8,2405.18 2621.8,2408.18 v1(2674.81,2408.18)
  Bottom Layer w5: v1(2674.81,2408.18) 2724.19,2408.18 R28.1@2727.19,2405.18
NetR29_1: R29.1 U7.3 | length 72.2
  Top Layer w5: R29.1@2166.43,2879.18 2175.43,2888.18 U7.3@2234.88,2888.18
NetR30_1: R30.1 U8.1 | length 36.4
  Bottom Layer w5: R30.1@685.81,3277.18 686.81,3276.18 U8.1@686.81,3241.18
NetR31_1: R31.1 U8.7 | length 54
  Bottom Layer w5: R31.1@507.81,3219.18 510.12,3221.5 U8.7@560.82,3221.5
NetR46_2: R46.2 U23.4 | length 101.9
  Bottom Layer w5: R46.2@1499.97,2569.66 1521.33,2569.66 1551.31,2539.68 1569.06,2539.68 1571.99,2536.75 U23.4@1571.99,2520.52
NetR47_1: R47.1 U23.3 | length 57.3
  Bottom Layer w5: R47.1@1500.43,2524.18 1504.09,2520.52 U23.3@1556.24,2520.52
NetR48_2: R48.2 U23.11 | length 90.4
  Bottom Layer w5: U23.11@1571.99,2461.46 1571.99,2429.68 1573.96,2427.72 1573.96,2403.28 1579.52,2397.72 R48.2@1579.52,2374.18
NetR49_2: R49.2 U23.6 | length 158.2
  Bottom Layer w5: R49.2@1500.43,2618.18 1530.97,2618.18 1583.31,2565.84 1603.49,2545.67 U23.6@1603.49,2520.52
NetR53_1: R53.1 R54.2 U26.2 | length 92.9
  Top Layer w5: R53.1@1240.43,3035.18 1241.43,3034.18 1241.43,2993.18 U26.2@1241.43,2942.66
NetTP1_1: TP1.1 U9.40 | length 237.6
  Bottom Layer w5: U9.40@812.32,2841.18 812.32,2873.75 823.64,2885.07 830.79,2885.07 844.65,2898.93 844.65,2928.38 859.5,2943.22 859.5,2993.84 883.47,3017.82 TP1.1@910.75,3017.82
NetTP7_1: TP7.1 U23.9 | length 72.7
  Bottom Layer w5: U23.9@1603.49,2461.46 1603.49,2439.5 1608.36,2434.63 TP7.1@1652.23,2434.63
OUT_0: R42.2 U21.3 | length 639.9
  Top Layer w5: U21.3@2023.26,2419.74 2023.53,2419.47 2023.53,2373.46 v1(2023.81,2373.18)
  Bottom Layer w5: R42.2@1495.38,2286.49 1495.38,2313.75 1526.31,2344.68 1654.47,2344.68 1698.47,2388.68 2008.31,2388.68 v1(2023.81,2373.18)
OUT_1: R43.2 U21.4 | length 498.7
  Top Layer w5: U21.4@1997.67,2419.74 1998.74,2418.67 1998.74,2355.25 v1(1999.81,2354.18)
  Bottom Layer w5: R43.2@1621.84,2286.49 1621.84,2316.21 1631.81,2326.18 1652.81,2326.18 1691.47,2364.84 1987.15,2364.84 1997.81,2354.18 v1(1999.81,2354.18)
OUT_2: R44.2 U21.5 | length 340.3
  Top Layer w5: v1(1969.81,2344.18) 1970.94,2345.32 1970.94,2418.61 U21.5@1972.08,2419.74
  Bottom Layer w5: R44.2@1753.19,2286.49 1753.19,2325.57 1772.31,2344.68 1969.31,2344.68 v1(1969.81,2344.18)
OUT_3: R45.2 U21.6 | length 178.9
  Top Layer w5: v1(1924.81,2325.18) 1925.81,2325.18 1946.49,2345.86 U21.6@1946.49,2419.74
  Bottom Layer w5: R45.2@1881.54,2286.49 1881.54,2311.42 1896.3,2326.18 1923.81,2326.18 v1(1924.81,2325.18)
TUSB_OUT1: R50.1 U23.7 U25.1 | length 207.1
  Bottom Layer w5: U23.7@1605.45,2498.87 1657.08,2498.87 1659.89,2501.67 1700.24,2501.67 1714.65,2516.08 U25.1@1742.94,2516.08 1793.96,2516.08 R50.1@1802.06,2524.18
TUSB_OUT2: R51.1 U23.8 U25.2 | length 212.5
  Bottom Layer w5: U23.8@1605.45,2483.12 1657.98,2483.12 1665.97,2491.11 1703.83,2491.11 1709.11,2496.39 U25.2@1742.94,2496.39 1772.91,2496.39 1798.12,2471.18 R51.1@1802.06,2471.18
USB_CC1: J5.A5 U23.1 U24.4 U24.7 | length 647.9
  Top Layer w5: U24.4@1480.53,2551.47 U24.7@1480.53,2518.59 1481.97,2517.16 1481.97,2502.7 1483.02,2501.65 1483.02,2475.15 v1(1485.42,2472.75) ; v1(1564.81,2558.18) 1564.3,2558.69 1564.3,2597.54 1581.45,2614.7 1581.45,2655.44 1589.35,2663.33 J5.A5@1589.35,2695.49
  Bottom Layer w5: U23.1@1554.27,2483.12 1499.3,2483.12 1488.93,2472.75 v1(1485.42,2472.75) 1457.37,2472.75 1435.19,2494.93 1415.89,2494.93 1403.31,2507.51 1403.31,2518.84 1403.08,2519.08 1403.08,2576.39 1404.7,2578.02 1404.7,2578.25 1416.42,2589.97 1533.02,2589.97 v1(1564.81,2558.18)
USB_CC2: J5.B5 U23.2 U24.5 U24.6 | length 558.4
  Top Layer w5: v1(1464.33,2494.18) 1462.29,2496.22 1462.29,2517.16 U24.6@1460.85,2518.59 U24.5@1460.85,2551.47 1460.85,2568.14 1436.81,2592.18 1420.65,2592.18 1402.31,2610.52 1402.31,2671.1 1425.84,2694.63 1425.84,2777.22 1450.81,2802.18 1521.81,2802.18 1528.32,2795.67 J5.B5@1528.32,2772.66
  Bottom Layer w5: v1(1464.33,2494.18) 1467.84,2494.18 1472.53,2498.87 U23.2@1554.27,2498.87
USB_D_N: J5.A7 J5.B7 U9.93 U24.2 U24.9 | length 844.7
  Top Layer w4: v1(1196.81,2348.31) 1200.03,2348.31 1206.15,2342.18 1249.67,2342.18 1283.3,2342.18 1482.67,2342.18 1524.75,2384.26 1524.75,2507.13 1522.4,2509.47 1521.84,2509.47 1519.9,2511.41 U24.9@1519.9,2518.59 1519.9,2525.78 1521.84,2527.72 1522.4,2527.72 1524.75,2530.06 1524.75,2540 1522.4,2542.35 1521.84,2542.35 1519.9,2544.28 U24.2@1519.9,2551.47 1519.9,2558.65 1521.84,2560.59 1522.4,2560.59 1524.75,2562.93 1524.75,2604.12 1551.81,2631.18 v1(1551.81,2650.18) 1553.81,2652.18 1553.81,2691.66 J5.A7@1549.98,2695.49
  Bottom Layer w4: v1(1196.81,2348.31) 1206.81,2338.31 1221.78,2338.31 1224.66,2341.18 U9.93@1249.33,2341.18 ; v1(1551.81,2650.18) 1575.57,2673.94 J5.B7@1575.57,2745.1
USB_D_P: J5.A6 J5.B6 U9.94 U24.1 U24.10 | length 903.1
  Top Layer w4: v1(1196.81,2318.31) 1206.44,2327.94 1210.68,2332.18 1224.44,2332.18 1227.64,2328.98 1227.64,2320.3 1230.84,2317.1 1240.44,2317.1 1243.64,2320.3 1243.64,2328.98 1246.84,2332.18 1256.44,2332.18 1259.64,2328.98 1259.64,2320.3 1262.84,2317.1 1272.44,2317.1 1275.64,2320.3 1275.64,2328.98 1278.84,2332.18 1283.3,2332.18 1486.81,2332.18 1534.75,2380.12 1534.75,2420.76 1534.75,2438.76 1537.95,2441.96 1544.32,2441.96 1547.52,2445.16 1547.52,2454.76 1544.32,2457.96 1537.95,2457.96 1534.75,2461.16 1534.75,2470.76 1537.95,2473.96 1544.32,2473.96 1547.52,2477.16 1547.52,2486.76 1544.32,2489.96 1537.95,2489.96 1534.75,2493.16 1534.75,2496.14 1534.75,2507.13 1537.09,2509.47 1537.65,2509.47 1539.59,2511.41 U24.10@1539.59,2518.59 1539.59,2525.78 1537.65,2527.72 1537.09,2527.72 1534.75,2530.06 1534.75,2540 1537.09,2542.35 1537.65,2542.35 1539.59,2544.28 U24.1@1539.59,2551.47 1539.59,2558.65 1537.65,2560.59 1537.09,2560.59 1534.75,2562.93 1534.75,2599.98 1566.31,2631.54 1566.31,2692.14 J5.A6@1569.66,2695.49 1569.66,2720.99 1545.55,2745.1 J5.B6@1544.07,2745.1
  Bottom Layer w4: v1(1196.81,2318.31) 1206.81,2328.31 1221.78,2328.31 1224.66,2325.43 U9.94@1249.33,2325.43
